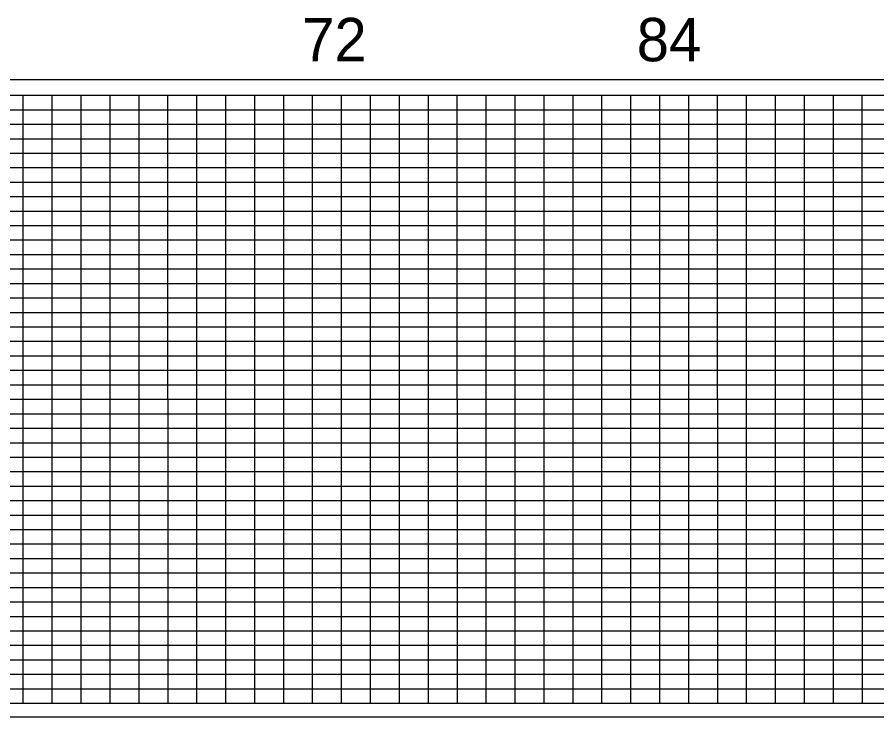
# Model space of a CAD drawing. Extents: x 1894907 to 1905782, y 740939 to 777025.
# Drawn here: x 1898121 to 1899607, y 775566 to 776774 of the extents above; entities that cross this region are included whole.
import ezdxf

# ---------------------------------------------------------------- set-up
doc = ezdxf.new("R2010")
doc.units = 0
doc.layers.add('RD_PD_WallFill', color=7, linetype='Continuous')
doc.layers.add('RD_SHT_IplotShp', color=7, linetype='Continuous')

msp = doc.modelspace()

# ---------------------------------------------------------------- linework, layer by layer
at = {"layer": 'RD_PD_WallFill'}
for p, q in [((1895081.6, 776639.1), (1900431.6, 776639.2)), ((1898131.6, 775589.2), (1898131.6, 776639.2)), ((1898181.7, 775589.1), (1898181.6, 776639.2)), ((1898231.6, 775589.2), (1898231.7, 776639.2)), ((1898281.6, 775589.2), (1898281.6, 776639.2)), ((1898331.6, 775589.2), (1898331.6, 776639.2)), ((1898381.7, 775589.2), (1898381.6, 776639.2)), ((1898431.7, 775589.2), (1898431.6, 776639.2)), ((1898481.6, 775589.1), (1898481.6, 776639.2)), ((1898531.7, 775589.1), (1898531.6, 776639.2)), ((1898581.7, 775589.2), (1898581.6, 776639.2)), ((1898631.6, 775589.2), (1898631.6, 776639.2)), ((1898681.6, 775589.2), (1898681.6, 776639.2)), ((1898731.7, 775589.2), (1898731.6, 776639.2)), ((1898781.6, 775589.2), (1898781.7, 776639.2)), ((1898831.6, 775589.2), (1898831.7, 776639.2)), ((1898881.7, 775589.2), (1898881.6, 776639.2)), ((1898931.7, 775589.2), (1898931.6, 776639.2)), ((1898981.7, 775589.2), (1898981.6, 776639.2)), ((1899031.7, 775589.2), (1899031.6, 776639.2)), ((1899081.7, 775589.2), (1899081.6, 776639.2)), ((1899131.7, 775589.2), (1899131.6, 776639.2)), ((1899181.7, 775589.2), (1899181.6, 776639.2)), ((1899231.7, 775589.2), (1899231.6, 776639.2)), ((1899281.7, 775589.2), (1899281.6, 776639.2)), ((1899331.7, 775589.2), (1899331.6, 776639.2)), ((1899381.7, 775589.2), (1899381.6, 776639.2)), ((1899431.7, 775589.2), (1899431.6, 776639.2)), ((1899481.7, 775589.2), (1899481.6, 776639.2)), ((1899531.7, 775589.2), (1899531.6, 776639.2)), ((1899581.7, 775589.2), (1899581.6, 776639.2)), ((1895531.6, 776614.1), (1900431.6, 776614.1)), ((1895531.6, 776589.1), (1900431.6, 776589.1)), ((1895531.6, 776564.1), (1900431.6, 776564.1)), ((1895531.6, 776539.2), (1900431.6, 776539.1)), ((1895531.6, 776514.1), (1900431.6, 776514.2)), ((1895081.6, 776489.1), (1900431.6, 776489.1)), ((1895081.6, 776464.1), (1900431.6, 776464.1)), ((1895081.6, 776439.1), (1900431.6, 776439.2)), ((1895081.6, 776414.2), (1900431.6, 776414.1)), ((1895081.6, 776389.2), (1900431.6, 776389.2)), ((1895081.6, 776364.1), (1900431.6, 776364.1)), ((1895081.6, 776339.1), (1900431.6, 776339.1)), ((1895081.6, 776314.2), (1900431.6, 776314.1)), ((1895081.6, 776289.1), (1900431.6, 776289.1)), ((1895081.6, 776264.2), (1900431.6, 776264.1)), ((1895081.6, 776239.1), (1900431.6, 776239.1)), ((1895081.6, 776214.1), (1900431.6, 776214.2)), ((1895081.6, 776189.1), (1900431.6, 776189.1)), ((1895081.6, 776164.1), (1900431.6, 776164.2)), ((1895081.6, 776139.1), (1900431.6, 776139.1)), ((1895081.6, 776114.1), (1900431.6, 776114.1)), ((1895081.6, 776089.2), (1900431.6, 776089.1)), ((1895081.6, 776064.1), (1900431.6, 776064.1)), ((1895081.6, 776039.1), (1900431.6, 776039.1)), ((1895081.6, 776014.1), (1900431.6, 776014.1)), ((1895081.6, 775989.1), (1900431.6, 775989.2)), ((1895081.6, 775964.1), (1900431.6, 775964.1)), ((1895081.6, 775939.1), (1900431.6, 775939.1)), ((1895081.6, 775914.1), (1900431.6, 775914.1)), ((1895081.6, 775889.1), (1900431.6, 775889.1)), ((1895081.6, 775864.1), (1900431.6, 775864.1)), ((1895081.6, 775839.1), (1900431.6, 775839.1)), ((1895081.6, 775814.1), (1900431.6, 775814.1)), ((1895081.6, 775789.1), (1900431.6, 775789.1)), ((1895081.6, 775764.1), (1900431.6, 775764.1)), ((1895081.6, 775739.1), (1900431.6, 775739.1)), ((1895081.6, 775714.1), (1900431.6, 775714.1)), ((1895081.6, 775689.1), (1900431.6, 775689.1)), ((1895081.6, 775664.1), (1900431.6, 775664.1)), ((1895081.6, 775639.1), (1900431.6, 775639.1)), ((1895131.6, 775614.1), (1900431.6, 775614.1)), ((1895081.6, 775589.1), (1900431.6, 775589.1))]:
    msp.add_line(p, q, dxfattribs=at)
at = {"layer": 'RD_SHT_IplotShp'}
msp.add_lwpolyline([(1895056.6, 775565.6), (1900456.6, 775565.6), (1900456.6, 776665.6), (1895056.6, 776665.6)], close=True, dxfattribs=at)

# ---------------------------------------------------------------- texts
at = {"layer": 'RD_PD_WallFill'}
for s, p in [('72', (1898613.5, 776697.8)), ('84', (1899191.7, 776697.8))]:
    msp.add_text(s, height=75, dxfattribs=at).set_placement(p)

doc.saveas('drawing.dxf')
